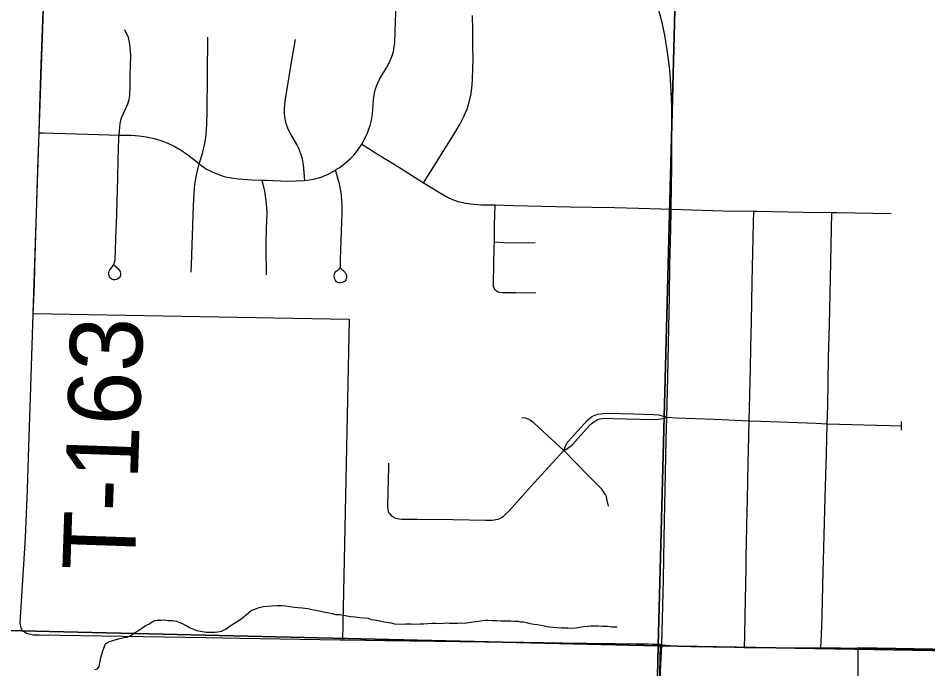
# Model space of a CAD drawing. Extents: x 0 to 34, y 0 to 22.
# Drawn here: x 5.883 to 6.597, y 16.369 to 16.879 of the extents above; entities that cross this region are included whole.
import ezdxf

# ---------------------------------------------------------------- set-up
doc = ezdxf.new("R2010")
doc.units = 0
for name, color, linetype in [('Default', 7, 'Continuous'), ('GM_X_City_Street', 7, 'Continuous'), ('GM_X_County_Road', 7, 'Continuous'), ('GM_X_Minor_River', 7, 'Continuous'), ('GM_X_Section', 7, 'Continuous'), ('GM_X_State_Route', 7, 'Continuous'), ('GM_X_Township_Road', 7, 'Continuous'), ('GM_X_Township_Road_Text', 7, 'Continuous')]:
    doc.layers.add(name, color=color, linetype=linetype)

msp = doc.modelspace()

# ---------------------------------------------------------------- linework, layer by layer
at = {"layer": 'Default'}
for points in [[(6.62511, 15.83621), (6.63591, 16.30343), (6.54257, 16.30557), (6.54257, 16.38549), (6.7626, 16.3814), (6.7778, 16.96235), (6.71516, 16.96317), (6.7165, 17.04135), (6.77819, 17.04108), (6.84668, 17.08571), (6.84666, 17.13495), (6.90683, 17.13323), (6.90779, 17.17565), (7.08937, 17.17153), (7.09183, 17.15641), (7.10858, 17.04866), (7.10953, 17.04219), (7.11751, 16.99147), (7.40369, 16.98523), (7.40131, 16.87363), (7.61677, 16.86855)], [(5.38506, 16.9971), (5.90615, 16.978), (5.90436, 16.93048), (5.89943, 16.78958), (5.89487, 16.64739), (6.14305, 16.64283), (6.13769, 16.39147), (6.38702, 16.38807), (6.37183, 15.73038)]]:
    msp.add_lwpolyline(points, dxfattribs=at)
at = {"layer": 'GM_X_City_Street'}
for points in [[(6.10815, 16.75157), (6.11506, 16.75273), (6.12094, 16.75423), (6.126, 16.75641), (6.13142, 16.75929), (6.13241, 16.7599), (6.13611, 16.76219), (6.14, 16.76512), (6.14411, 16.7688), (6.14706, 16.77187), (6.14969, 16.77521), (6.15294, 16.78008), (6.15543, 16.78457), (6.15741, 16.78904), (6.15948, 16.79481), (6.16053, 16.79892), (6.16135, 16.8037), (6.1617, 16.8073), (6.16219, 16.81472), (6.16276, 16.81911), (6.1637, 16.82344), (6.16489, 16.82705), (6.16679, 16.83108), (6.16944, 16.83537), (6.17272, 16.84055), (6.17493, 16.84485), (6.17656, 16.84876), (6.1778, 16.8528), (6.17848, 16.85634), (6.17884, 16.85995), (6.1795, 16.87661), (6.18007, 16.89502)], [(6.20136, 16.74988), (6.20628, 16.75775), (6.22506, 16.78776), (6.23018, 16.79621), (6.23322, 16.80225), (6.23559, 16.80791), (6.23733, 16.81315), (6.23858, 16.81851), (6.2394, 16.82396), (6.23986, 16.83009), (6.24016, 16.84061), (6.24029, 16.84618), (6.24002, 16.85739), (6.23997, 16.86975), (6.23985, 16.88101)], [(5.95851, 16.68529), (5.96046, 16.6837), (5.96251, 16.68176), (5.96334, 16.68008), (5.9636, 16.67886), (5.96355, 16.67763), (5.9632, 16.67644), (5.96253, 16.6754), (5.96162, 16.67456), (5.96052, 16.67398), (5.95931, 16.6737), (5.95808, 16.67378), (5.95691, 16.67419), (5.95589, 16.6749), (5.95509, 16.67585), (5.95457, 16.67697), (5.95436, 16.67818), (5.95444, 16.67942), (5.95478, 16.68061), (5.95535, 16.68171), (5.95724, 16.6842), (5.95858, 16.68627), (5.95899, 16.68743), (5.9593, 16.68926), (5.95971, 16.69734), (5.96023, 16.71412), (5.96037, 16.71533), (5.9603, 16.71598), (5.96044, 16.7172), (5.96138, 16.75326), (5.96185, 16.76818), (5.96235, 16.78497), (5.9625, 16.78731), (5.96294, 16.79363), (5.9635, 16.79793), (5.96442, 16.80089), (5.96698, 16.80657), (5.96928, 16.81167), (5.97035, 16.81523), (5.97079, 16.81829), (5.97113, 16.82574), (5.97122, 16.83383), (5.97159, 16.84968), (5.97126, 16.85609), (5.9706, 16.8602), (5.96977, 16.86382), (5.96697, 16.86991)], [(6.02535, 16.7648), (6.02786, 16.7729), (6.02978, 16.78072), (6.03077, 16.78748), (6.03144, 16.79553), (6.03171, 16.80548), (6.03206, 16.86394)], [(6.10815, 16.75157), (6.1072, 16.7638), (6.10633, 16.76861), (6.10519, 16.77268), (6.10363, 16.77665), (6.10198, 16.7799), (6.09718, 16.78793), (6.09525, 16.79193), (6.09395, 16.79553), (6.0929, 16.79985), (6.0923, 16.80427), (6.09221, 16.8081), (6.09272, 16.81376), (6.09779, 16.84448), (6.10092, 16.86223)], [(5.89966, 16.78902), (5.90301, 16.78893), (5.94638, 16.78772), (5.9625, 16.78731), (5.97189, 16.78707), (5.97815, 16.78664), (5.98375, 16.78582), (5.9899, 16.78456), (5.99535, 16.78298), (6.00066, 16.78098), (6.00579, 16.77856), (6.01071, 16.77575), (6.01541, 16.77259), (6.02181, 16.76756), (6.02535, 16.7648), (6.02813, 16.76263), (6.03117, 16.76062), (6.0355, 16.75842), (6.0412, 16.75609), (6.04585, 16.75461), (6.05064, 16.75362), (6.05612, 16.75292), (6.0666, 16.75222), (6.07473, 16.75193), (6.0778, 16.75182), (6.09457, 16.75113), (6.10815, 16.75157)], [(6.15294, 16.78008), (6.15936, 16.77616), (6.16253, 16.77421), (6.18257, 16.76176), (6.20136, 16.74988), (6.20197, 16.74949), (6.21255, 16.74292), (6.22016, 16.73858), (6.22418, 16.73672), (6.22836, 16.73525), (6.23326, 16.73401), (6.23826, 16.73323), (6.24638, 16.73269), (6.2576, 16.73244), (6.27186, 16.73211), (6.31657, 16.73108), (6.35136, 16.73035), (6.36998, 16.72999), (6.38771, 16.72946), (6.3958, 16.72922)], [(6.01912, 16.67984), (6.01924, 16.68545), (6.02085, 16.73215), (6.02161, 16.74583), (6.0221, 16.75005), (6.02295, 16.75464), (6.02458, 16.76155), (6.02535, 16.7648)], [(6.13662, 16.68256), (6.13906, 16.68039), (6.13983, 16.67951), (6.14049, 16.67851), (6.14093, 16.67737), (6.14101, 16.67613), (6.14066, 16.67434), (6.14032, 16.67363), (6.13986, 16.67305), (6.13931, 16.67254), (6.13823, 16.67191), (6.13751, 16.67166), (6.13659, 16.67142), (6.13562, 16.67136), (6.13472, 16.6715), (6.13382, 16.67178), (6.13305, 16.67222), (6.13229, 16.67319), (6.13178, 16.67433), (6.13151, 16.67553), (6.13138, 16.67664), (6.13151, 16.67828), (6.13172, 16.67912), (6.13226, 16.68012), (6.13275, 16.68063), (6.1344, 16.68172), (6.13532, 16.68227), (6.13583, 16.68273), (6.13621, 16.6839), (6.13632, 16.68981), (6.13733, 16.71931), (6.13752, 16.7262), (6.13751, 16.72814), (6.13749, 16.73184), (6.13725, 16.73633), (6.13664, 16.74224), (6.13517, 16.75046), (6.1348, 16.75171), (6.13241, 16.7599)], [(6.07829, 16.6777), (6.07824, 16.67955), (6.07808, 16.68572), (6.07796, 16.69062), (6.07792, 16.69615), (6.07797, 16.70296), (6.07821, 16.7141), (6.07858, 16.72585), (6.07843, 16.73079), (6.07786, 16.7357), (6.07674, 16.74333), (6.07473, 16.75193)], [(6.25698, 16.70344), (6.25719, 16.71742), (6.25737, 16.7243), (6.2576, 16.73244)], [(6.3958, 16.72922), (6.4365, 16.72794), (6.46065, 16.7277), (6.46325, 16.72768), (6.49932, 16.72692), (6.5217, 16.72661), (6.52606, 16.72655), (6.56831, 16.72587)], [(6.45326, 16.38556), (6.45345, 16.39547), (6.45374, 16.41039), (6.45449, 16.44766), (6.45466, 16.45698), (6.45494, 16.4663), (6.45519, 16.48121), (6.45559, 16.50171), (6.45626, 16.52968), (6.45678, 16.5508), (6.45706, 16.56327), (6.45796, 16.60423), (6.45823, 16.62101), (6.45882, 16.64089), (6.45937, 16.67196), (6.46045, 16.71858), (6.46065, 16.7277)], [(6.51327, 16.38514), (6.51366, 16.39515), (6.51425, 16.41006), (6.51479, 16.43427), (6.51658, 16.50318), (6.51752, 16.53732), (6.51826, 16.56091), (6.51865, 16.57519), (6.5193, 16.61246), (6.51988, 16.63852), (6.52078, 16.67515), (6.5217, 16.72661)], [(6.28945, 16.6633), (6.27384, 16.6636), (6.2633, 16.66368), (6.26127, 16.66375), (6.25985, 16.66414), (6.25855, 16.66494), (6.25755, 16.66595), (6.25675, 16.66722), (6.25633, 16.66863), (6.25619, 16.67129), (6.25692, 16.69934), (6.25698, 16.70344)], [(6.25698, 16.70344), (6.2641, 16.70313), (6.26472, 16.7031), (6.28893, 16.70266)], [(6.31145, 16.53999), (6.31275, 16.54332), (6.31358, 16.54498), (6.31425, 16.54606), (6.31498, 16.54692), (6.33002, 16.56372), (6.33193, 16.56537), (6.33298, 16.56608), (6.33407, 16.56675), (6.33536, 16.56737), (6.33673, 16.56785), (6.33836, 16.56833), (6.34026, 16.56875), (6.34236, 16.56905), (6.34441, 16.56913), (6.36614, 16.56862), (6.382, 16.56817), (6.38592, 16.5678), (6.38933, 16.56689), (6.3923, 16.56593)], [(6.27861, 16.56585), (6.28108, 16.56541), (6.28256, 16.56495), (6.28379, 16.56439), (6.28526, 16.5636), (6.28747, 16.56201), (6.29218, 16.55763), (6.31145, 16.53999)], [(6.31145, 16.53999), (6.31461, 16.54164), (6.31658, 16.5431), (6.31771, 16.54415), (6.31821, 16.54471), (6.33166, 16.55952), (6.33291, 16.56079), (6.33391, 16.5617), (6.33533, 16.56266), (6.33685, 16.56347), (6.33831, 16.56413), (6.34003, 16.56469), (6.34184, 16.56504), (6.34366, 16.56514), (6.35023, 16.56505), (6.38192, 16.56424), (6.38567, 16.56447), (6.38758, 16.5647), (6.39032, 16.56526), (6.3923, 16.56593)], [(6.3923, 16.56593), (6.39998, 16.56563), (6.4298, 16.56446), (6.45706, 16.56327), (6.46647, 16.56286), (6.50936, 16.56125), (6.51826, 16.56091), (6.57642, 16.55937)], [(6.57648, 16.55581), (6.57642, 16.55937), (6.57645, 16.56273)], [(6.17485, 16.49037), (6.17603, 16.489), (6.1772, 16.48808), (6.17812, 16.48743), (6.1795, 16.48684), (6.18074, 16.48652), (6.18244, 16.48626), (6.18441, 16.48606), (6.19695, 16.48605), (6.2243, 16.48577), (6.25039, 16.48538), (6.25545, 16.48541), (6.25805, 16.48572), (6.25982, 16.48611), (6.26132, 16.4867), (6.26302, 16.48768), (6.2642, 16.48847), (6.26557, 16.4896), (6.26833, 16.49225), (6.28824, 16.51454), (6.31145, 16.53999)], [(6.34664, 16.49625), (6.3456, 16.50091), (6.34486, 16.50349), (6.344, 16.50557), (6.34301, 16.50734), (6.34147, 16.50928), (6.33902, 16.51205), (6.3305, 16.52034), (6.31145, 16.53999)], [(6.17485, 16.49037), (6.17426, 16.49135), (6.17387, 16.49233), (6.17361, 16.49364), (6.17341, 16.49547), (6.17359, 16.50783), (6.17413, 16.52694), (6.1741, 16.52998)]]:
    msp.add_lwpolyline(points, dxfattribs=at)
at = {"layer": 'GM_X_County_Road'}
for points in [[(6.3883, 16.38756), (6.40105, 16.38643), (6.41149, 16.38634), (6.44559, 16.38561), (6.45326, 16.38556)], [(6.45326, 16.38556), (6.50393, 16.38516), (6.51327, 16.38514)], [(6.51327, 16.38514), (6.52874, 16.38511), (6.54186, 16.38495)], [(6.54186, 16.38495), (6.5428, 16.38494), (6.57161, 16.38454), (6.59956, 16.38412), (6.66477, 16.38305), (6.72688, 16.38212), (6.76436, 16.38147)]]:
    msp.add_lwpolyline(points, dxfattribs=at)
at = {"layer": 'GM_X_Minor_River'}
for points in [[(5.94335, 16.36809), (5.94565, 16.36878), (5.94684, 16.37065), (5.9473, 16.3733), (5.94818, 16.37745), (5.94985, 16.38273), (5.95109, 16.38612), (5.95191, 16.38837), (5.95424, 16.38983), (5.95768, 16.39087), (5.9619, 16.39227), (5.96649, 16.39328), (5.96878, 16.39359), (5.97109, 16.39467), (5.9738, 16.39649), (5.97573, 16.39758), (5.98115, 16.40122), (5.9831, 16.40269), (5.98578, 16.40375), (5.9885, 16.40557), (5.99043, 16.40666), (5.99234, 16.40698), (5.99537, 16.4069), (5.99804, 16.4072), (6.00107, 16.40673), (6.00448, 16.40663), (6.0075, 16.40617), (6.01013, 16.40495), (6.01313, 16.40372), (6.01576, 16.40251), (6.01837, 16.40091), (6.02099, 16.3997), (6.02325, 16.39887), (6.02513, 16.39844), (6.02778, 16.39798), (6.0308, 16.39751), (6.03422, 16.39741), (6.03726, 16.39733), (6.03992, 16.39763), (6.04298, 16.3983), (6.04645, 16.4001), (6.04955, 16.4023), (6.05304, 16.40448), (6.05652, 16.40666), (6.05962, 16.40885), (6.06234, 16.41106), (6.06429, 16.4129), (6.06624, 16.41436), (6.07239, 16.41685), (6.07544, 16.41752), (6.07887, 16.41781), (6.08268, 16.41807), (6.08648, 16.41834), (6.09028, 16.41824), (6.09332, 16.41815), (6.09634, 16.41768), (6.10012, 16.41719), (6.10315, 16.41673), (6.10618, 16.41664), (6.11073, 16.41613), (6.11374, 16.41528), (6.11715, 16.4148), (6.12054, 16.41394), (6.12431, 16.41308), (6.12734, 16.41261), (6.1296, 16.41216), (6.13262, 16.41131), (6.13565, 16.41123), (6.13868, 16.41076), (6.14132, 16.4103), (6.14397, 16.40985), (6.14775, 16.40936), (6.15154, 16.40887), (6.15496, 16.40877), (6.15798, 16.40831), (6.16024, 16.40748), (6.16288, 16.40702), (6.16591, 16.40656), (6.1693, 16.4057), (6.1727, 16.40522), (6.17573, 16.40475), (6.17874, 16.4039), (6.1833, 16.40377), (6.18748, 16.40403), (6.19166, 16.40391), (6.19507, 16.40381), (6.1985, 16.4041), (6.20153, 16.40401), (6.20458, 16.4043), (6.20801, 16.40458), (6.21105, 16.4045), (6.21522, 16.40438), (6.21827, 16.40467), (6.22168, 16.40457), (6.22548, 16.40446), (6.22813, 16.40439)], [(6.22813, 16.40439), (6.2308, 16.40469), (6.23346, 16.40461), (6.24185, 16.40589), (6.2449, 16.40619), (6.24757, 16.40649), (6.24985, 16.4068), (6.25175, 16.40675), (6.25517, 16.40665), (6.25858, 16.40655), (6.262, 16.40645), (6.26541, 16.40636), (6.26769, 16.40629), (6.26997, 16.40623), (6.273, 16.40614), (6.27566, 16.40606), (6.27755, 16.40563), (6.27982, 16.40556), (6.28209, 16.40511), (6.28472, 16.40428), (6.28813, 16.4038), (6.29078, 16.40334), (6.2938, 16.40288), (6.29607, 16.40243), (6.29795, 16.402), (6.30022, 16.40155), (6.30288, 16.40148), (6.30628, 16.401), (6.3097, 16.4009), (6.31235, 16.40082), (6.31463, 16.40076), (6.31767, 16.40067), (6.32071, 16.40096), (6.32376, 16.40125), (6.3272, 16.40192), (6.33062, 16.4022), (6.33291, 16.40251), (6.33519, 16.40245), (6.33823, 16.40236), (6.34164, 16.40226), (6.34582, 16.40214), (6.34922, 16.40166), (6.35112, 16.40161), (6.3534, 16.40154)]]:
    msp.add_lwpolyline(points, dxfattribs=at)
at = {"layer": 'GM_X_Section'}
for points in [[(5.41251, 17.40958), (6.41184, 17.39355), (6.38559, 16.38675), (5.38574, 16.41038)], [(6.41184, 17.39355), (7.41005, 17.37616), (7.38494, 16.36973), (6.38559, 16.38675)], [(5.38005, 16.41012), (5.38574, 16.41038), (6.38559, 16.38675), (6.36308, 15.34539), (5.35524, 15.36699)], [(6.38559, 16.38675), (7.38494, 16.36973), (7.37037, 15.30881), (6.36308, 15.34539)]]:
    msp.add_lwpolyline(points, close=True, dxfattribs=at)
at = {"layer": 'GM_X_State_Route'}
for points in [[(6.39582, 16.73024), (6.39626, 16.76267), (6.39636, 16.79315), (6.39623, 16.8103), (6.39552, 16.82652), (6.3947, 16.83823), (6.39307, 16.8504), (6.39097, 16.86396), (6.38888, 16.8745), (6.38644, 16.88423), (6.38354, 16.89454), (6.3798, 16.9048), (6.37554, 16.91593), (6.37506, 16.91709), (6.37137, 16.92575), (6.36678, 16.93541), (6.36512, 16.93852), (6.36175, 16.94485), (6.36077, 16.94652)], [(6.3883, 16.38756), (6.38966, 16.43866), (6.39022, 16.47145), (6.3919, 16.54806), (6.3923, 16.56593), (6.39302, 16.59765), (6.39437, 16.66116), (6.39481, 16.68526), (6.39526, 16.70346), (6.39571, 16.72617), (6.3958, 16.72922), (6.39582, 16.73024)], [(6.36983, 15.73023), (6.37038, 15.78187), (6.3709, 15.81168), (6.37199, 15.85205), (6.37341, 15.9005), (6.37503, 15.95142), (6.37592, 15.98186), (6.37738, 16.03404), (6.37862, 16.07752), (6.37992, 16.12597), (6.38068, 16.15578), (6.3827, 16.21602), (6.38401, 16.26074), (6.38459, 16.2796), (6.38513, 16.29739), (6.38703, 16.36074), (6.3883, 16.38756)]]:
    msp.add_lwpolyline(points, dxfattribs=at)
at = {"layer": 'GM_X_Township_Road'}
for points in [[(5.89966, 16.78902), (5.90028, 16.80905), (5.9014, 16.8429), (5.90313, 16.89113), (5.90451, 16.92802), (5.90467, 16.93183)], [(5.8951, 16.64684), (5.89598, 16.6697), (5.89639, 16.68338), (5.89878, 16.76052), (5.89966, 16.78902)], [(5.88675, 16.3988), (5.88597, 16.39999), (5.88561, 16.401), (5.88525, 16.4019), (5.88502, 16.40304), (5.8849, 16.4044), (5.88898, 16.47171), (5.89051, 16.50942), (5.8916, 16.54293), (5.89287, 16.5814), (5.8951, 16.64684)], [(5.88675, 16.3988), (5.88816, 16.39766), (5.8899, 16.39679), (5.89171, 16.39619), (5.89332, 16.39579), (5.89499, 16.39545), (5.89714, 16.39526), (5.89989, 16.39526), (6.03061, 16.39332), (6.05758, 16.39287), (6.1359, 16.39154), (6.13706, 16.39153)], [(6.13706, 16.39153), (6.14012, 16.39148), (6.17115, 16.39102), (6.24953, 16.38996), (6.28002, 16.38949), (6.32605, 16.38879), (6.37763, 16.38828), (6.3883, 16.38756)]]:
    msp.add_lwpolyline(points, dxfattribs=at)

# ---------------------------------------------------------------- texts
at = {"layer": 'GM_X_Township_Road_Text'}
msp.add_text('T-163', height=0.056818, rotation=88.04784, dxfattribs=at).set_placement((5.97471, 16.44498))

doc.saveas('drawing.dxf')
